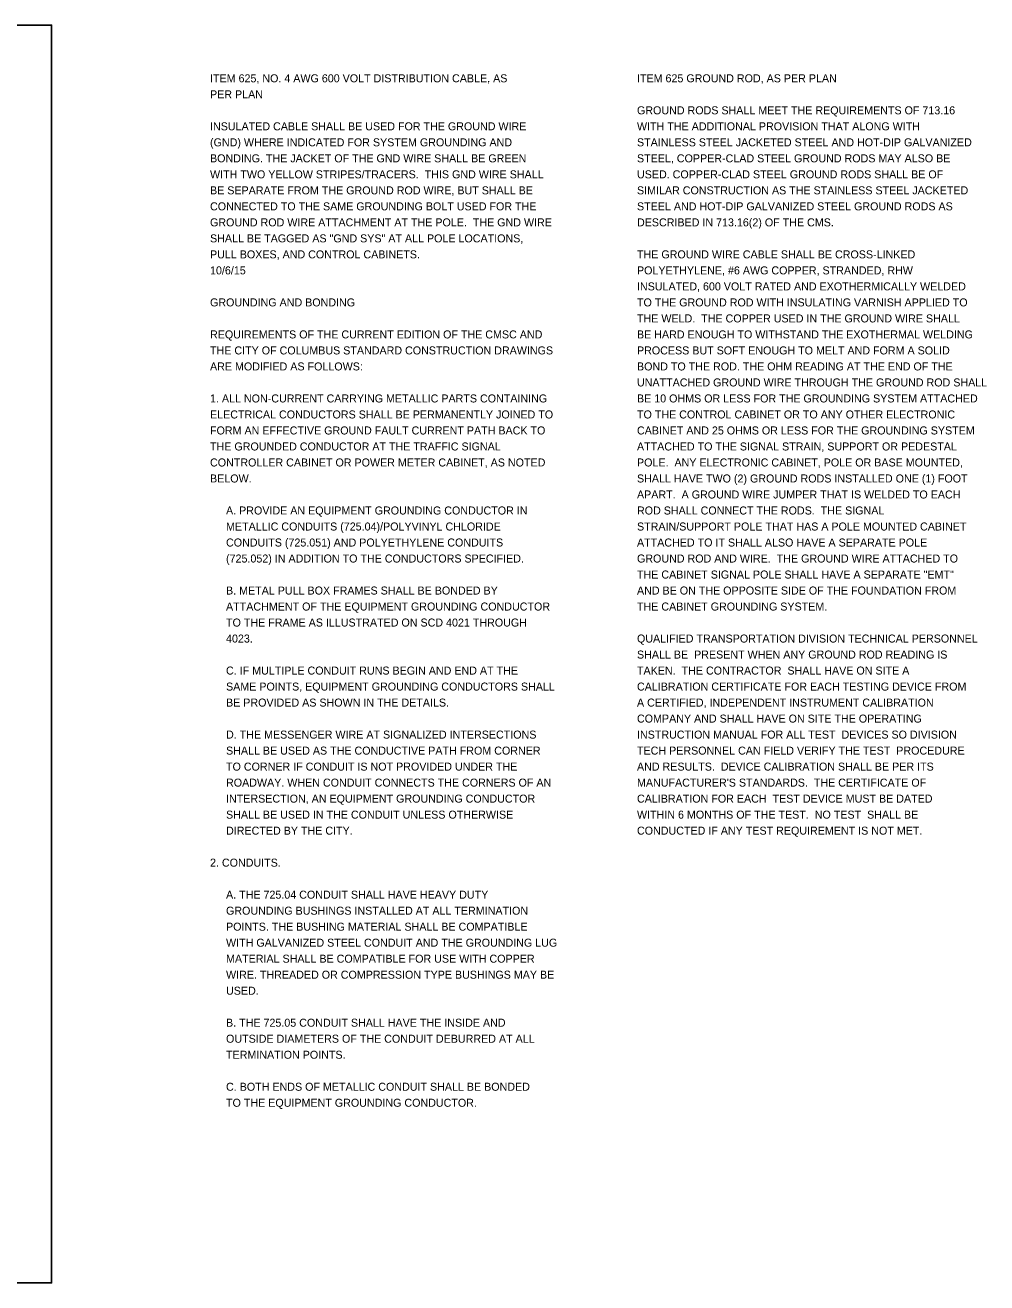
# Model space of a CAD drawing. Extents: x -62 to 50, y -16 to 14.
# Drawn here: x 33.03 to 49.85, y -7.51 to 14.49 of the extents above; entities that cross this region are included whole.
import ezdxf

# ---------------------------------------------------------------- set-up
doc = ezdxf.new("R2010")
doc.units = 0
for name, color, linetype in [('SH_Cut_Line', 7, 'Continuous'), ('SH_Data', 7, 'Continuous'), ('SH_Text', 7, 'Continuous')]:
    doc.layers.add(name, color=color, linetype=linetype)

msp = doc.modelspace()

# ---------------------------------------------------------------- linework, layer by layer
at = {"layer": 'SH_Cut_Line'}
msp.add_lwpolyline([(-0.506, -7.508), (33.494, -7.508), (33.494, 14.492), (-0.506, 14.492)], close=True, dxfattribs=at)

# ---------------------------------------------------------------- texts
at = {"layer": 'SH_Data'}
for s, p in [('ITEM 625, NO. 4 AWG 600 VOLT DISTRIBUTION CABLE, AS ', (36.265, 13.492)), ('PER PLAN', (36.265, 13.212)), ('INSULATED CABLE SHALL BE USED FOR THE GROUND WIRE ', (36.265, 12.652)), ('(GND) WHERE INDICATED FOR SYSTEM GROUNDING AND ', (36.265, 12.372)), ('BONDING. THE JACKET OF THE GND WIRE SHALL BE GREEN ', (36.265, 12.092)), ('WITH TWO YELLOW STRIPES/TRACERS.  THIS GND WIRE SHALL ', (36.265, 11.812)), ('BE SEPARATE FROM THE GROUND ROD WIRE, BUT SHALL BE ', (36.265, 11.532)), ('CONNECTED TO THE SAME GROUNDING BOLT USED FOR THE ', (36.265, 11.252)), ('GROUND ROD WIRE ATTACHMENT AT THE POLE.  THE GND WIRE ', (36.265, 10.972)), ('SHALL BE TAGGED AS "GND SYS" AT ALL POLE LOCATIONS, ', (36.265, 10.692)), ('PULL BOXES, AND CONTROL CABINETS. ', (36.265, 10.412)), ('10/6/15', (36.265, 10.132)), ('GROUNDING AND BONDING', (36.265, 9.572)), ('REQUIREMENTS OF THE CURRENT EDITION OF THE CMSC AND ', (36.265, 9.012)), ('THE CITY OF COLUMBUS STANDARD CONSTRUCTION DRAWINGS ', (36.265, 8.732)), ('ARE MODIFIED AS FOLLOWS:', (36.265, 8.452)), ('1. ALL NON-CURRENT CARRYING METALLIC PARTS CONTAINING ', (36.265, 7.892)), ('ELECTRICAL CONDUCTORS SHALL BE PERMANENTLY JOINED TO ', (36.265, 7.612)), ('FORM AN EFFECTIVE GROUND FAULT CURRENT PATH BACK TO ', (36.265, 7.332)), ('THE GROUNDED CONDUCTOR AT THE TRAFFIC SIGNAL ', (36.265, 7.052)), ('CONTROLLER CABINET OR POWER METER CABINET, AS NOTED ', (36.265, 6.772)), ('BELOW.', (36.265, 6.492)), ('A. PROVIDE AN EQUIPMENT GROUNDING CONDUCTOR IN ', (36.545, 5.932)), ('METALLIC CONDUITS (725.04)/POLYVINYL CHLORIDE ', (36.545, 5.652)), ('CONDUITS (725.051) AND POLYETHYLENE CONDUITS ', (36.545, 5.372)), ('(725.052) IN ADDITION TO THE CONDUCTORS SPECIFIED.', (36.545, 5.092)), ('B. METAL PULL BOX FRAMES SHALL BE BONDED BY ', (36.545, 4.532)), ('ATTACHMENT OF THE EQUIPMENT GROUNDING CONDUCTOR ', (36.545, 4.252)), ('TO THE FRAME AS ILLUSTRATED ON SCD 4021 THROUGH ', (36.545, 3.972)), ('4023.', (36.545, 3.692)), ('C. IF MULTIPLE CONDUIT RUNS BEGIN AND END AT THE ', (36.545, 3.132)), ('SAME POINTS, EQUIPMENT GROUNDING CONDUCTORS SHALL ', (36.545, 2.852)), ('BE PROVIDED AS SHOWN IN THE DETAILS.', (36.545, 2.572)), ('D. THE MESSENGER WIRE AT SIGNALIZED INTERSECTIONS ', (36.545, 2.012)), ('SHALL BE USED AS THE CONDUCTIVE PATH FROM CORNER ', (36.545, 1.732)), ('TO CORNER IF CONDUIT IS NOT PROVIDED UNDER THE ', (36.545, 1.452)), ('ROADWAY. WHEN CONDUIT CONNECTS THE CORNERS OF AN ', (36.545, 1.172)), ('INTERSECTION, AN EQUIPMENT GROUNDING CONDUCTOR ', (36.545, 0.892)), ('SHALL BE USED IN THE CONDUIT UNLESS OTHERWISE ', (36.545, 0.612)), ('DIRECTED BY THE CITY.', (36.545, 0.332)), ('2. CONDUITS.', (36.265, -0.228)), ('A. THE 725.04 CONDUIT SHALL HAVE HEAVY DUTY ', (36.545, -0.788)), ('GROUNDING BUSHINGS INSTALLED AT ALL TERMINATION ', (36.545, -1.068)), ('POINTS. THE BUSHING MATERIAL SHALL BE COMPATIBLE ', (36.545, -1.348)), ('WITH GALVANIZED STEEL CONDUIT AND THE GROUNDING LUG ', (36.545, -1.628)), ('MATERIAL SHALL BE COMPATIBLE FOR USE WITH COPPER ', (36.545, -1.908)), ('WIRE. THREADED OR COMPRESSION TYPE BUSHINGS MAY BE ', (36.545, -2.188)), ('USED.', (36.545, -2.468)), ('B. THE 725.05 CONDUIT SHALL HAVE THE INSIDE AND ', (36.545, -3.028)), ('OUTSIDE DIAMETERS OF THE CONDUIT DEBURRED AT ALL ', (36.545, -3.308)), ('TERMINATION POINTS.', (36.545, -3.588)), ('C. BOTH ENDS OF METALLIC CONDUIT SHALL BE BONDED ', (36.545, -4.148)), ('TO THE EQUIPMENT GROUNDING CONDUCTOR.', (36.545, -4.428))]:
    msp.add_text(s, height=0.14, dxfattribs=at).set_placement(p)
at = {"layer": 'SH_Text'}
for s, p in [('ITEM 625 GROUND ROD, AS PER PLAN ', (43.734, 13.492)), ('GROUND RODS SHALL MEET THE REQUIREMENTS OF 713.16 ', (43.734, 12.932)), ('WITH THE ADDITIONAL PROVISION THAT ALONG WITH ', (43.734, 12.652)), ('STAINLESS STEEL JACKETED STEEL AND HOT-DIP GALVANIZED ', (43.734, 12.372)), ('STEEL, COPPER-CLAD STEEL GROUND RODS MAY ALSO BE ', (43.734, 12.092)), ('USED. COPPER-CLAD STEEL GROUND RODS SHALL BE OF ', (43.734, 11.812)), ('SIMILAR CONSTRUCTION AS THE STAINLESS STEEL JACKETED ', (43.734, 11.532)), ('STEEL AND HOT-DIP GALVANIZED STEEL GROUND RODS AS ', (43.734, 11.252)), ('DESCRIBED IN 713.16(2) OF THE CMS. ', (43.734, 10.972)), ('THE GROUND WIRE CABLE SHALL BE CROSS-LINKED ', (43.734, 10.412)), ('POLYETHYLENE, #6 AWG COPPER, STRANDED, RHW ', (43.734, 10.132)), ('INSULATED, 600 VOLT RATED AND EXOTHERMICALLY WELDED ', (43.734, 9.852)), ('TO THE GROUND ROD WITH INSULATING VARNISH APPLIED TO ', (43.734, 9.572)), ('THE WELD.  THE COPPER USED IN THE GROUND WIRE SHALL ', (43.734, 9.292)), ('BE HARD ENOUGH TO WITHSTAND THE EXOTHERMAL WELDING ', (43.734, 9.012)), ('PROCESS BUT SOFT ENOUGH TO MELT AND FORM A SOLID ', (43.734, 8.732)), ('BOND TO THE ROD. THE OHM READING AT THE END OF THE ', (43.734, 8.452)), ('UNATTACHED GROUND WIRE THROUGH THE GROUND ROD SHALL ', (43.734, 8.172)), ('BE 10 OHMS OR LESS FOR THE GROUNDING SYSTEM ATTACHED ', (43.734, 7.892)), ('TO THE CONTROL CABINET OR TO ANY OTHER ELECTRONIC ', (43.734, 7.612)), ('CABINET AND 25 OHMS OR LESS FOR THE GROUNDING SYSTEM ', (43.734, 7.332)), ('ATTACHED TO THE SIGNAL STRAIN, SUPPORT OR PEDESTAL ', (43.734, 7.052)), ('POLE.  ANY ELECTRONIC CABINET, POLE OR BASE MOUNTED, ', (43.734, 6.772)), ('SHALL HAVE TWO (2) GROUND RODS INSTALLED ONE (1) FOOT  ', (43.734, 6.492)), ('APART.  A GROUND WIRE JUMPER THAT IS WELDED TO EACH ', (43.734, 6.212)), ('ROD SHALL CONNECT THE RODS.  THE SIGNAL ', (43.734, 5.932)), ('STRAIN/SUPPORT POLE THAT HAS A POLE MOUNTED CABINET ', (43.734, 5.652)), ('ATTACHED TO IT SHALL ALSO HAVE A SEPARATE POLE ', (43.734, 5.372)), ('GROUND ROD AND WIRE.  THE GROUND WIRE ATTACHED TO ', (43.734, 5.092)), ('THE CABINET SIGNAL POLE SHALL HAVE A SEPARATE "EMT" ', (43.734, 4.812)), ('AND BE ON THE OPPOSITE SIDE OF THE FOUNDATION FROM ', (43.734, 4.532)), ('THE CABINET GROUNDING SYSTEM. ', (43.734, 4.252)), ('QUALIFIED TRANSPORTATION DIVISION TECHNICAL PERSONNEL ', (43.734, 3.692)), ('SHALL BE  PRESENT WHEN ANY GROUND ROD READING IS ', (43.734, 3.412)), ('TAKEN.  THE CONTRACTOR  SHALL HAVE ON SITE A ', (43.734, 3.132)), ('CALIBRATION CERTIFICATE FOR EACH TESTING DEVICE FROM ', (43.734, 2.852)), ('A CERTIFIED, INDEPENDENT INSTRUMENT CALIBRATION ', (43.734, 2.572)), ('COMPANY AND SHALL HAVE ON SITE THE OPERATING ', (43.734, 2.292)), ('INSTRUCTION MANUAL FOR ALL TEST  DEVICES SO DIVISION ', (43.734, 2.012)), ('TECH PERSONNEL CAN FIELD VERIFY THE TEST  PROCEDURE ', (43.734, 1.732)), ('AND RESULTS.  DEVICE CALIBRATION SHALL BE PER ITS  ', (43.734, 1.452)), ("MANUFACTURER'S STANDARDS.  THE CERTIFICATE OF ", (43.734, 1.172)), ('CALIBRATION FOR EACH  TEST DEVICE MUST BE DATED ', (43.734, 0.892)), ('WITHIN 6 MONTHS OF THE TEST.  NO TEST  SHALL BE ', (43.734, 0.612)), ('CONDUCTED IF ANY TEST REQUIREMENT IS NOT MET.', (43.734, 0.332))]:
    msp.add_text(s, height=0.14, dxfattribs=at).set_placement(p)

doc.saveas('drawing.dxf')
